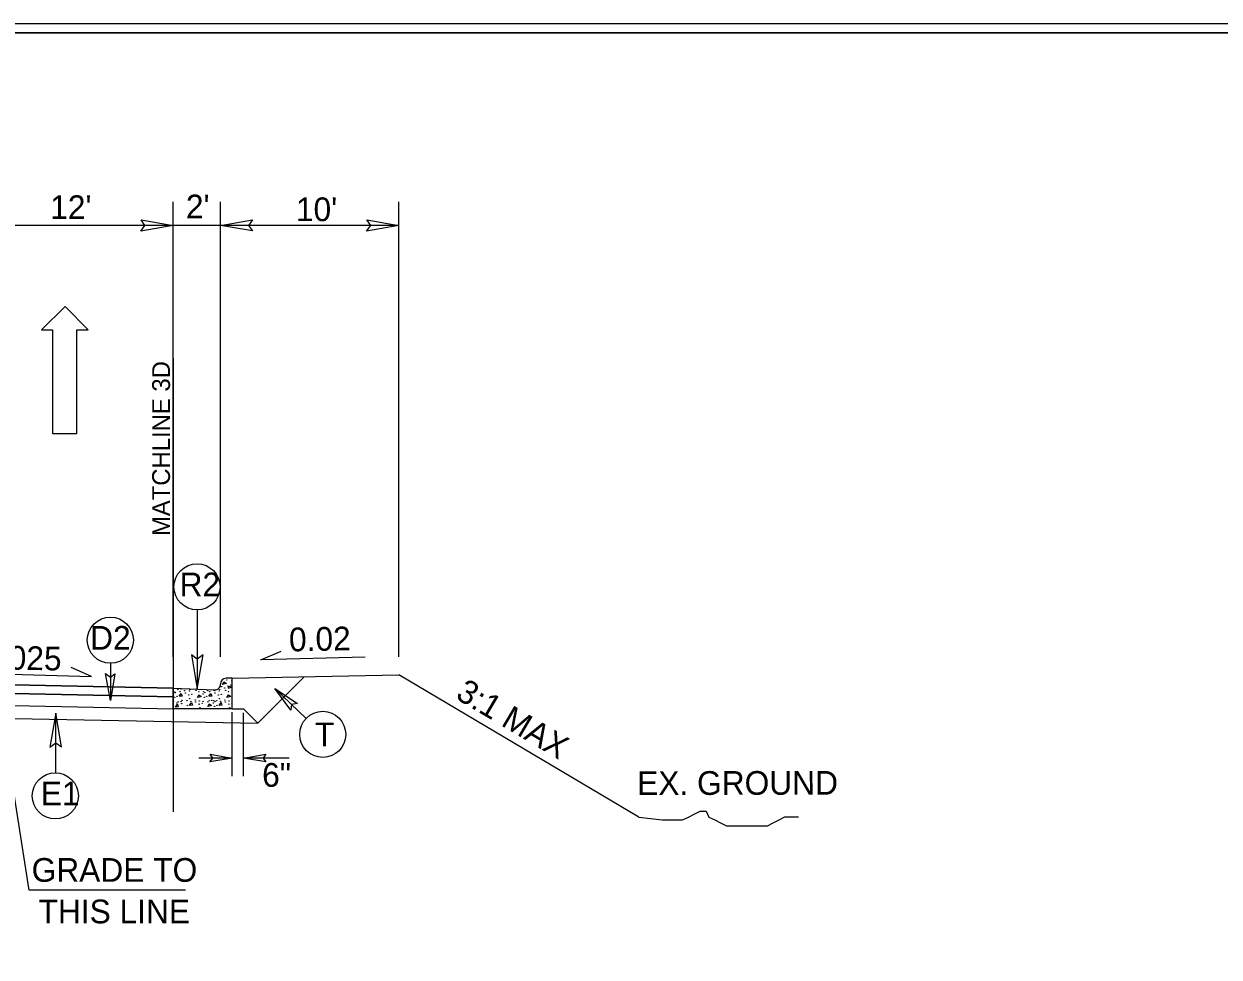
# Model space of a CAD drawing. Extents: x 2320980 to 2456309, y 595047 to 606177.
# Drawn here: x 2455910.9 to 2455978, y 596904.3 to 596956.6 of the extents above; entities that cross this region are included whole.
import ezdxf

# ---------------------------------------------------------------- set-up
doc = ezdxf.new("R2010")
doc.units = 0
for name, color, linetype in [('Matchline', 7, 'Continuous'), ('Matchline Text', 7, 'Continuous'), ('Old_Level_1', 7, 'Continuous'), ('Old_Level_20', 7, 'Continuous'), ('Old_Level_21', 7, 'Continuous'), ('Old_Level_3', 7, 'Continuous'), ('Prop Dimension Text', 7, 'Continuous'), ('Prop Lane Arrow CELL', 7, 'Continuous'), ('Sheet Plan CELL', 7, 'Continuous'), ('Sheet Plot Border Inside CELL', 7, 'Continuous'), ('Typical Berm CELL', 7, 'Continuous'), ('Typical Curb CELL', 7, 'Continuous'), ('Typical Hinge Slope Arterial CELL', 7, 'Continuous'), ('Typical ID Circle CELL', 7, 'Continuous'), ('Typical Pavement Slope CELL', 7, 'Continuous'), ('Typical Terminator CELL', 7, 'Continuous')]:
    doc.layers.add(name, color=color, linetype=linetype)

msp = doc.modelspace()

# ---------------------------------------------------------------- linework, layer by layer
at = {"layer": 'Matchline'}
msp.add_line((2455919.308, 596937.837), (2455919.308, 596912.397), dxfattribs=at)
at = {"layer": 'Old_Level_21'}
for p, q in [((2455919.308, 596921.101), (2455919.308, 596946.606)), ((2455921.968, 596921.101), (2455921.968, 596946.606)), ((2455931.968, 596921.101), (2455931.968, 596946.606)), ((2455921.968, 596945.276), (2455893.868, 596945.276)), ((2455931.968, 596945.276), (2455921.968, 596945.276)), ((2455945.431, 596912.113), (2455931.968, 596920.088)), ((2455911.239, 596908.016), (2455909.732, 596917.689)), ((2455922.632, 596914.409), (2455922.632, 596917.999)), ((2455923.265, 596914.409), (2455923.265, 596917.953)), ((2455919.998, 596908.016), (2455911.239, 596908.016))]:
    msp.add_line(p, q, dxfattribs=at)
at = {"layer": 'Old_Level_3'}
for p, q in [((2455895.308, 596919.334), (2455919.308, 596918.86)), ((2455904.243, 596918.478), (2455919.308, 596918.181))]:
    msp.add_line(p, q, dxfattribs=at)
at = {"layer": 'Prop Dimension Text'}
for p, q in [((2455915.792, 596920.731), (2455915.792, 596918.648)), ((2455926.768, 596917.641), (2455925.01, 596919.322)), ((2455922.632, 596915.421), (2455920.745, 596915.421)), ((2455925.827, 596915.421), (2455923.265, 596915.421))]:
    msp.add_line(p, q, dxfattribs=at)
for points in [[(2455930.09, 596921.08), (2455924.234, 596920.919), (2455925.371, 596921.407)], [(2455908.881, 596920.159), (2455914.737, 596919.999), (2455913.6, 596920.487)]]:
    msp.add_lwpolyline(points, dxfattribs=at)
for centre in [(2455920.653, 596925.016), (2455915.792, 596922.023), (2455927.703, 596916.747), (2455912.705, 596913.299)]:
    msp.add_circle(centre, 1.293, dxfattribs=at)
at = {"layer": 'Prop Lane Arrow CELL'}
for p, q in [((2455913.251, 596940.738), (2455911.921, 596939.429)), ((2455914.54, 596939.429), (2455913.251, 596940.738)), ((2455911.921, 596939.429), (2455912.545, 596939.429)), ((2455912.545, 596939.429), (2455912.545, 596933.61)), ((2455913.916, 596933.61), (2455913.916, 596939.429)), ((2455913.916, 596939.429), (2455914.54, 596939.429)), ((2455912.545, 596933.61), (2455913.916, 596933.61))]:
    msp.add_line(p, q, dxfattribs=at)
at = {"layer": 'Sheet Plan CELL'}
for points in [[(2455742.104, 596746.076), (2455742.099, 596956.071), (2456002.097, 596956.079), (2456002.099, 596926.066), (2456042.107, 596926.064), (2456042.107, 596746.076)], [(2456042.112, 596956.076), (2455742.104, 596956.076), (2455742.104, 596746.076), (2456042.107, 596746.076)]]:
    msp.add_lwpolyline(points, close=True, dxfattribs=at)
at = {"layer": 'Sheet Plot Border Inside CELL'}
msp.add_lwpolyline([(2455711.407, 596745.574), (2456044.604, 596745.576), (2456044.607, 596956.574), (2455711.407, 596956.574)], close=True, dxfattribs=at)
at = {"layer": 'Typical Berm CELL'}
for p, q in [((2455922.632, 596919.893), (2455931.968, 596920.088)), ((2455922.632, 596918.176), (2455923.255, 596918.176))]:
    msp.add_line(p, q, dxfattribs=at)
at = {"layer": 'Typical Curb CELL'}
for p, q in [((2455922.632, 596919.893), (2455922.286, 596919.893)), ((2455922.632, 596918.176), (2455922.632, 596919.893)), ((2455919.308, 596919.339), (2455921.635, 596919.242)), ((2455919.654, 596918.882), (2455919.769, 596919.041)), ((2455919.769, 596919.041), (2455919.815, 596918.89)), ((2455921.316, 596918.882), (2455921.43, 596919.041)), ((2455921.43, 596919.041), (2455921.475, 596918.89)), ((2455922.081, 596919.541), (2455922.164, 596919.693)), ((2455922.301, 596919.593), (2455922.081, 596919.541)), ((2455922.164, 596919.693), (2455922.301, 596919.593)), ((2455922.379, 596919.45), (2455922.401, 596919.329)), ((2455922.584, 596919.39), (2455922.379, 596919.45)), ((2455922.401, 596919.329), (2455922.584, 596919.39)), ((2455919.442, 596918.281), (2455919.557, 596918.44)), ((2455919.557, 596918.44), (2455919.603, 596918.289)), ((2455919.815, 596918.89), (2455919.654, 596918.882)), ((2455920.232, 596918.373), (2455920.347, 596918.532)), ((2455920.392, 596918.381), (2455920.232, 596918.373)), ((2455920.347, 596918.532), (2455920.392, 596918.381)), ((2455920.672, 596918.814), (2455920.755, 596918.966)), ((2455920.892, 596918.867), (2455920.672, 596918.814)), ((2455920.755, 596918.966), (2455920.892, 596918.867)), ((2455921.25, 596918.305), (2455921.333, 596918.457)), ((2455921.47, 596918.357), (2455921.25, 596918.305)), ((2455921.475, 596918.89), (2455921.316, 596918.882)), ((2455921.333, 596918.457), (2455921.47, 596918.357)), ((2455921.894, 596918.373), (2455922.007, 596918.532)), ((2455922.053, 596918.381), (2455921.894, 596918.373)), ((2455922.007, 596918.532), (2455922.053, 596918.381)), ((2455922.333, 596918.814), (2455922.416, 596918.966)), ((2455922.553, 596918.867), (2455922.333, 596918.814)), ((2455922.416, 596918.966), (2455922.553, 596918.867)), ((2455922.632, 596918.176), (2455919.308, 596918.176)), ((2455919.603, 596918.289), (2455919.442, 596918.281))]:
    msp.add_line(p, q, dxfattribs=at)
for centre in [(2455922.326, 596919.792), (2455922.614, 596919.747), (2455919.352, 596919.141), (2455919.427, 596919.095), (2455919.571, 596919.261), (2455919.7, 596919.148), (2455919.761, 596919.284), (2455919.958, 596919.2), (2455919.996, 596919.065), (2455920.232, 596919.179), (2455920.254, 596919.246), (2455920.596, 596919.208), (2455920.755, 596919.141), (2455921.014, 596919.141), (2455921.088, 596919.095), (2455921.232, 596919.205), (2455921.361, 596919.148), (2455921.62, 596919.2), (2455921.658, 596919.065), (2455921.893, 596919.179), (2455921.916, 596919.246), (2455922.04, 596919.42), (2455922.199, 596919.352), (2455922.257, 596919.208), (2455922.417, 596919.141), (2455922.546, 596919.504), (2455919.322, 596918.601), (2455919.33, 596919.012), (2455919.405, 596918.822), (2455919.526, 596918.502), (2455919.533, 596918.882), (2455919.602, 596918.571), (2455919.761, 596918.586), (2455919.785, 596918.464), (2455919.814, 596918.662), (2455920.087, 596918.632), (2455920.111, 596918.373), (2455920.194, 596918.951), (2455920.239, 596918.746), (2455920.315, 596918.594), (2455920.361, 596918.989), (2455920.551, 596918.678), (2455920.574, 596918.555), (2455920.771, 596918.441), (2455920.778, 596918.624), (2455920.938, 596918.479), (2455920.983, 596918.601), (2455920.991, 596919.012), (2455921.067, 596918.822), (2455921.195, 596918.882), (2455921.263, 596918.571), (2455921.333, 596918.631), (2455921.475, 596918.662), (2455921.569, 596918.502), (2455921.591, 596918.631), (2455921.666, 596918.586), (2455921.749, 596918.632), (2455921.772, 596918.373), (2455921.855, 596918.951), (2455921.9, 596918.746), (2455921.976, 596918.594), (2455922.022, 596918.989), (2455922.212, 596918.678), (2455922.235, 596918.555), (2455922.433, 596918.441), (2455922.439, 596918.624), (2455922.6, 596918.479), (2455920.817, 596918.237), (2455921.644, 596918.312), (2455922.478, 596918.237)]:
    msp.add_circle(centre, 0.0107, dxfattribs=at)
for centre, start, end in [((2455922.286, 596919.575), 90, 180), ((2455921.649, 596919.56), 267.61554, 0)]:
    msp.add_arc(centre, 0.319, start, end, dxfattribs=at)
at = {"layer": 'Typical Hinge Slope Arterial CELL'}
msp.add_lwpolyline([(2455945.431, 596912.113), (2455946.742, 596911.951), (2455947.069, 596911.951), (2455947.561, 596911.951), (2455947.889, 596911.951), (2455948.217, 596912.114), (2455948.544, 596912.279), (2455948.872, 596912.443), (2455949.2, 596912.443), (2455949.364, 596912.114), (2455949.692, 596911.951), (2455950.02, 596911.787), (2455950.347, 596911.624), (2455950.675, 596911.624), (2455951.003, 596911.624), (2455951.33, 596911.624), (2455951.658, 596911.624), (2455951.986, 596911.624), (2455952.313, 596911.624), (2455952.641, 596911.624), (2455952.969, 596911.788), (2455953.296, 596911.952), (2455953.624, 596912.115), (2455954.116, 596912.116), (2455954.388, 596912.116)], dxfattribs=at)
at = {"layer": 'Typical ID Circle CELL'}
for p, q in [((2455920.665, 596923.723), (2455920.665, 596919.306)), ((2455912.731, 596914.597), (2455912.731, 596917.935))]:
    msp.add_line(p, q, dxfattribs=at)
at = {"layer": 'Typical Pavement Slope CELL'}
for p, q in [((2455895.308, 596919.819), (2455919.308, 596919.339)), ((2455919.308, 596919.339), (2455895.308, 596919.819)), ((2455926.668, 596919.977), (2455924.061, 596917.37)), ((2455895.308, 596919.334), (2455919.308, 596918.86)), ((2455919.308, 596918.86), (2455908.256, 596919.078)), ((2455919.308, 596918.86), (2455919.308, 596919.339)), ((2455904.243, 596918.478), (2455919.308, 596918.181)), ((2455919.308, 596918.181), (2455919.308, 596918.86)), ((2455904.243, 596917.766), (2455924.061, 596917.37)), ((2455923.255, 596918.176), (2455924.061, 596917.37))]:
    msp.add_line(p, q, dxfattribs=at)
at = {"layer": 'Typical Terminator CELL'}
for points in [[(2455917.512, 596945.585), (2455919.308, 596945.276), (2455917.502, 596944.957), (2455917.732, 596945.276)], [(2455923.763, 596944.967), (2455921.968, 596945.276), (2455923.773, 596945.595), (2455923.544, 596945.276)], [(2455930.172, 596945.585), (2455931.968, 596945.276), (2455930.162, 596944.957), (2455930.392, 596945.276)], [(2455920.338, 596921.201), (2455920.665, 596919.306), (2455921.001, 596921.212), (2455920.665, 596920.969)], [(2455916.049, 596920.144), (2455915.792, 596918.648), (2455915.526, 596920.152), (2455915.792, 596919.961)], [(2455925.913, 596918.101), (2455925.01, 596919.322), (2455926.281, 596918.474), (2455925.959, 596918.414)], [(2455913.057, 596916.04), (2455912.731, 596917.935), (2455912.394, 596916.029), (2455912.731, 596916.271)], [(2455921.385, 596915.636), (2455922.632, 596915.421), (2455921.378, 596915.199), (2455921.538, 596915.421)], [(2455924.512, 596915.206), (2455923.265, 596915.421), (2455924.519, 596915.643), (2455924.359, 596915.421)]]:
    msp.add_lwpolyline(points, close=True, dxfattribs=at)

# ---------------------------------------------------------------- texts
at = {"layer": 'Matchline Text'}
msp.add_text('MATCHLINE 3D', height=1, rotation=90, dxfattribs=at).set_placement((2455919.137, 596927.864))
at = {"layer": 'Old_Level_1'}
msp.add_text('EX. GROUND', height=1.33, rotation=0.08974, dxfattribs=at).set_placement((2455945.338, 596913.349))
at = {"layer": 'Old_Level_20'}
for s, p in [('R2', (2455919.675, 596924.486)), ('T', (2455927.265, 596916.082)), ('E1', (2455911.894, 596912.77))]:
    msp.add_text(s, height=1.33, dxfattribs=at).set_placement(p)
msp.add_text('D2', height=1.33, rotation=359.99718, dxfattribs=at).set_placement((2455914.658, 596921.494))
at = {"layer": 'Old_Level_21'}
for s, p in [("12'", (2455912.417, 596945.635)), ("10'", (2455926.198, 596945.517)), ('6"', (2455924.304, 596913.81)), ('GRADE TO', (2455911.376, 596908.482)), ('THIS LINE', (2455911.763, 596906.155))]:
    msp.add_text(s, height=1.33, dxfattribs=at).set_placement(p)
for s, rotation, p in [("2'", 0.00016, (2455920.028, 596945.672)), ('0.02', 1.14561, (2455925.825, 596921.395)), ('0.025', 358.85439, (2455908.594, 596920.412)), ('3:1 MAX', 329.36155, (2455935.093, 596918.786))]:
    msp.add_text(s, height=1.33, rotation=rotation, dxfattribs=at).set_placement(p)

doc.saveas('drawing.dxf')
